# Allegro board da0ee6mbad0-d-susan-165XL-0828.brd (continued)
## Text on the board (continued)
User.45: C1 | C2 | R197 | R199 | C3 | T1 | R6 | R4 | TP1 | R12 | R11 | R10 | R13 | C4 | C5 | C6 | TP2 | R18 | R26 | R27 | R28 | R29 | R30 | R31 | R32 | C20 | C22 | C34 | C39 | C40 | R40 | C46 | C49 | C51 | C52 | C53 | C54 | C56 | C57 | C58 | C60 | C62 | C67 | R56 | R60 | C70 | R62 | R63 | R64 | R65 | R66 | R67 | R68 | C72 | C73 | C74 | R75 | C78 | C79 | D3 | R90 | R91 | C80 | R93 | C81 | R94 | T3 | R99 | R101 | R103 | C87 | PR63 | PR65 | PR64 | R106 | TP60 | TP59 | TP61 | R109 | C92 | R114 | TP5 | PC5 | TP8 | TP7 | PC4 | PC9 | C96 | PR6 | PR7 | PC12 | PC14 | PC15 | PC17 | PC18 | PC20 | PC21 | PC22 | PC19 | PC23 | PR18 | TP11 | TP12 | R121 | R122 | R123 | R124 | R125 | R126 | R127 | R128 | R134 | R135 | R136 | R137 | R138 | R139 | R140 | R141 | PR152 | PR153 | R149 | R150 | C102 | R151 | R148 | PC27 | R161 | C111 | C112 | C113 | R166 | R167 | C375 | TP14 | PC30 | TP18 | TP20 | TP23 | TP30 | C122 | C121 | TP28 | TP26 | TP24 | C345 | R382 | C340 | C343 | C341 | C344 | C342 | PR39 | R400 | C369 | R191 | R186 | R185 | C362 | C361 | R190 | C371 | TP40 | TP34 | TP37 | TP41 | TP36 | TP31 | TP35 | TP39 | TP33 | C366 | C365 | TP32 | C370 | R390 | TP38 | R189 | R188 | PR43 | R207 | R9 | C137 | C140 | R208 | C139 | C138 | C142 | C149 | C148 | C150 | L5 | C147 | R220 | R221 | R218 | C145 | C146 | C141 | C143 | C144 | C152 | C161 | C162 | R224 | R223 | C153 | C154 | C155 | C159 | PR47 | PR49 | C172 | C173 | C174 | R243 | R244 | R245 | R246 | C170 | C171 | C175 | C176 | C177 | C178 | C179 | R247 | R248 | R249 | R250 | R258 | R259 | R260 | C184 | C185 | C186 | R262 | R263 | C188 | C204 | L6 | TP43 | C211 | C214 | C215 | TP44 | C225 | C241 | C239 | C240 | C242 | C243 | C247 | C246 | C244 | C245 | C226 | C221 | C254 | TP46 | TP54 | TP55 | TP45 | TP50 | TP49 | C255 | C256 | C257 | TP47 | TP53 | TP48 | C258 | TP52 | C260 | TP51 | C261 | C262 | C263 | C265 | C267 | C269 | C271 | C272 | C273 | TP56 | C275 | C274 | TP57 | PC44 | C276 | R312 | R313 | R314 | C282 | C283 | C284 | C285 | C286 | C287 | C288 | C292 | R317 | R318 | R321 | R322 | R325 | R328 | PC47 | PR74 | PR75 | PR76 | PR81 | PC74 | R329 | PR88 | PR86 | PC73 | PR87 | PC81 | PR91 | R331 | PR115 | PR55 | PR108 | PC104 | PR109 | PR110 | PR111 | PR112 | PC119 | PC120 | PC123 | PC124 | PC125 | PC128 | PC132 | PR123 | PR124 | PR125 | PR126 | PR127 | PR128 | PC134 | PR136 | PR133 | PR134 | PC133 | PR140 | PR141 | PR139 | PC135 | PR142 | C310 | C314 | R364 | C322 | C321 | C318 | C324 | R378 | C332 | C337 | L16 | C349 | TP62 | TP63 | R384 | C355 | C364 | C363 | C368 | L29 | C374 | L30 | C373 | C358 | 4 | 3 | 6 | TP27 | TP29 | U28 | PD4 | PR143 | PL21 | PL22 | C356 | R3 | R196 | C200 | R14 | C196 | R15 | C7 | C8 | C9 | C10 | C11 | C12 | C13 | C14 | C15 | C16 | R19 | R20 | R21 | R22 | R23 | R24 | C17 | C18 | R286 | C19 | R285 | T2 | R33 | C23 | C24 | C25 | C26 | C21 | C27 | C28 | C30 | C29 | C31 | C32 | C33 | R664 | C35 | C41 | C37 | C38 | C36 | R36 | C43 | C45 | R38 | C44 | R39 | C48 | R41 | C47 | R44 | R45 | C50 | C55 | R46 | R48 | R49 | C59 | R50 | C61 | R52 | C65 | C64 | C66 | R54 | C68 | R55 | R58 | R57 | R61 | R69 | R72 | R73 | R74 | R79 | R80 | R83 | R84 | C77 | R86 | R88 | R89 | R92 | R95 | R96 | R337 | C377 | R97 | C83 | R98 | C378 | C84 | R100 | C85 | R102 | C437 | C86 | R104 | C447 | C452 | C88 | R410 | R105 | C89 | C458 | R107 | C90 | R108 | C91 | C466 | R110 | C93 | C756 | R111 | T4 | R112 | T5 | TP4 | C94 | PC3 | TP6 | D4 | C95 | PR114 | PC8 | PC7 | PR107 | R115 | PC10 | PC11 | PR54 | PC13 | C97 | PC16 | R116 | R117 | R118 | R119 | R120 | PC24 | PC25 | PC26 | PR19 | C98 | C99 | R129 | R130 | R133 | R142 | R143 | PR147 | R144 | PR146 | TP13 | R145 | PR145 | PC137 | C100 | R146 | C101 | R147 | C107 | R154 | C103 | R152 | C104 | C105 | R153 | R156 | C106 | L1 | R155 | R159 | R160 | D7 | C108 | R157 | D8 | R162 | C109 | C114 | C376 | R168 | L2 | R169 | R404 | R170 | T6 | C115 | R407 | R171 | C116 | R406 | PR23 | PR24 | C117 | T7 | PR27 | C118 | PC28 | PC29 | T8 | C119 | C120 | TP15 | TP16 | PC31 | TP17 | R175 | PC32 | T9 | R177 | TP19 | PC33 | PR30 | R178 | PC34 | TP21 | PR32 | TP22 | PR34 | TP25 | PR36 | PR35 | PC35 | C125 | R181 | R182 | T10 | R183 | R184 | T11 | T12 | T13 | C126 | C127 | C128 | T14 | T15 | PR38 | PC40 | PC37 | PR41 | PC38 | PR42 | C134 | C133 | PD1 | R193 | R192 | PC36 | PC39 | C129 | C130 | C132 | C367 | C131 | C135 | C136 | R195 | R209 | R205 | T16 | R210 | R211 | R217 | PC41 | T17 | R225 | R219 | TP42 | R206 | R214 | R215 | R216 | C151 | PR44 | C82 | R213 | PR45 | PC43 | R227 | T18 | R222 | C160 | R229 | PC42 | R235 | R236 | C163 | C164 | R231 | R232 | R233 | R234 | C165 | C167 | C166 | R237 | C168 | R238 | R239 | R240 | R241 | C169 | R242 | R251 | C180 | C181 | C182 | C183 | R252 | R253 | R254 | R255 | R256 | R257 | R264 | R265 | R266 | C187 | C189 | C190 | R261 | C192 | C193 | C194 | C191 | C195 | R267 | R268 | C198 | C197 | C199 | R269 | R270 | C201 | C202 | C203 | R271 | R272 | R273 | C205 | R274 | R276 | C206 | C207 | R277 | R278 | C209 | L7 | R279 | C210 | R280 | C212 | C213 | R281 | R282 | C216 | R283 | R284 | C217 | C218 | C219 | L8 | C220 | C222 | C223 | C224 | C228 | C227 | C230 | C229 | L9 | C231 | C232 | C236 | C237 | C235 | C234 | C238 | C248 | C249 | C251 | C250 | C252 | C253 | R289 | C259 | R290 | R291 | R293 | R296 | PR50 | R297 | PR51 | R298 | C266 | PR52 | C268 | R302 | R303 | C270 | R306 | R305 | R307 | R402 | PR53 | R308 | C277 | C278 | C279 | C280 | C281 | C289 | TP58 | C290 | R316 | C291 | R326 | R323 | R324 | C293 | C294 | PR57 | PC45 | C295 | PC46 | C296 | PC48 | PR61 | PC53 | PC71 | PR83 | PR84 | C297 | PR94 | PC80 | PR96 | PR99 | R330 | PC86 | R332 | R333 | PC93 | R334 | R336 | R335 | R338 | C298 | C299 | R340 | R341 | R342 | R343 | C301 | C302 | R345 | C303 | PC121 | R348 | R349 | R350 | PR116 | PC126 | PC131 | PR132 | PR129 | SS1 | SS2 | PR135 | C307 | PR144 | C306 | C305 | C313 | C311 | C304 | C312 | C315 | C316 | C317 | C320 | R359 | C323 | R362 | C325 | C319 | R369 | C328 | R366 | C327 | C326 | C331 | C329 | R370 | C334 | R379 | C336 | C330 | C339 | R380 | C335 | C338 | C346 | L21 | C350 | L22 | C351 | C352 | L23 | C353 | L24 | C354 | R385 | C372 | L31 | L28 | C357 | C359 | SS3 | HOLE1 | HOLE3 | HOLE2 | 2 | Q1 | Q22 | Q3 | Q2 | HOLE4 | Q4 | Q5 | Q18 | PC1 | PC2 | Q6 | PQ1 | Q8 | F1 | Q9 | Q7 | 5 | PQ13 | PQ12 | 8 | HOLE5 | Y1 | Q10 | HOLE6 | PQ2 | PQ3 | PQ4 | L4 | HOLE13 | Q13 | Q14 | Q15 | Q16 | C156 | C157 | PQ5 | HOLE9 | HOLE7 | U30 | Y4 | PU3 | PC51 | PC52 | PC49 | PC50 | PL1 | PL2 | PC54 | PC55 | PL5 | PC56 | PL3 | PL4 | PC68 | PC70 | PC69 | PC76 | PC75 | PC77 | PC85 | PC89 | PC90 | PC91 | PL15 | Q17 | PL16 | PC97 | PC98 | PC110 | PC105 | PC106 | PC107 | PC108 | PC109 | PC118 | PU8 | 10 | D9 | HOLE10 | LED3 | U1 | U2 | HOLE12 | 74 | SW2 | 20 | U3 | SW3 | C42 | 60 | C69 | C71 | CN1 | C75 | U4 | R85 | 31 | 30 | U5 | SW4 | E | C | A | D | B | U7 | U8 | CN3 | 1 | 19 | HOLE11 | 25 | 36 | D6 | D5 | 24 | 37 | U10 | U11 | 7 | 13 | 48 | HE1 | C110 | H | F | U37 | J | G | 9 | J1 | U12 | PU1 | C123 | C124 | L3 | C347 | C348 | 11 | CN4 | 12 | U14 | 21 | CN5 | U15 | PAD1 | U16 | U17 | U20 | U18 | U19 | U21 | CN6 | PU2 | 75 | CN7 | P | K | M | T | U | R | N | L | AH | AG | AF | AE | AD | AC | U22 | AB | AA | U23 | U24 | U25 | Y2 | U26 | 15 | U27 | 17 | 16 | 14 | 59 | 58 | 57 | 56 | CN8 | 55 | 54 | 53 | 52 | 51 | 50 | 49 | 47 | 46 | 44 | 45 | 43 | 40 | 41 | 39 | 33 | C264 | 29 | U29 | CN9 | Y3 | AL | AP | BM | AY | BC | BF | BJ | W | AU | BR | BV | PQ7 | PQ8 | PR666 | PQ9 | PD2 | 18 | PL6 | PU5 | PC79 | PU6 | PC82 | PC83 | PC84 | PC87 | PC88 | PC99 | PC100 | PC101 | PC102 | PC103 | U31 | PC111 | PC112 | PC113 | PC114 | PC115 | PC116 | PC117 | U32 | PC122 | PL19 | PL20 | PU7 | PR119 | PC129 | PC130 | PC127 | PR130 | C308 | C309 | R355 | U33 | U34 | C333 | CN12 | CN13 | L27 | CN15 | U36 | CT1 | CN14 | U35 | CT2 | Q12 | Q11 | U13 | SW1 | LED1 | R663 | D1 | C76 | D2 | PC6 | PR12 | RP1 | PR151 | R164 | PR1 | PR120 | Q23 | PQ6 | HOLE8 | C158 | PC57 | PC58 | PC59 | PC60 | PC61 | PC62 | PC63 | PC64 | PC65 | PC66 | PL7 | PQ10 | PL8 | PL9 | PC72 | PC78 | PL10 | PL11 | PL12 | PL13 | PL14 | PC94 | PC95 | PL17 | PL18 | PQ11 | PC136 | LED2 | PAD2 | CN2 | Y | V | L10 | L11 | L12 | L13 | R667 | L14 | PD3 | PR79 | PC67 | PU4 | PC92 | PC96 | C300 | CN10 | CN11 | C360 | R7 | C758 | C757 | R87 | PR149 | PR150 | PR20 | R668 | R408 | R397 | R394 | R393 | R392 | R391 | R200 | R275 | R299 | R300 | R309 | R310 | R304 | R319 | PR67 | PR68 | PR80 | PR100 | R356 | R357 | R358 | R367 | L15 | R398 | R399 | R17 | R34 | R35 | R37 | R42 | R70 | R81 | R113 | PR3 | PR4 | PR8 | PR16 | PR148 | PR29 | PR31 | PR33 | R204 | R212 | R311 | R228 | R292 | R294 | R295 | R315 | PR58 | PR60 | PR85 | PR89 | PR93 | R339 | R346 | R347 | R361 | R372 | R376 | R381 | L18 | L20 | R388 | R1 | R198 | R669 | R43 | R47 | R59 | R77 | R78 | PR2 | PR14 | PR17 | R131 | R132 | R670 | PR22 | R411 | PR25 | R179 | R180 | R187 | R8 | R201 | R202 | R230 | R301 | R320 | PR66 | PR71 | PR69 | PR70 | PR77 | PR137 | PR138 | R352 | R353 | R354 | L25 | L26 | R396 | R395 | R401 | R2 | R16 | R25 | R53 | R71 | R76 | R82 | R158 | R163 | R172 | PR26 | R173 | PR28 | R174 | R176 | PR37 | R383 | R194 | R203 | R226 | R327 | PR59 | PR92 | PR95 | R344 | PR117 | PR118 | PR122 | R351 | R360 | R363 | R365 | R368 | R371 | R374 | R377 | R375 | R373 | L17 | L19 | R387 | R389 | R386 | XY-Check acute:Aug 28 11:05:46 2013 | XY-Check cline width:Aug 28 11:13:00 2013 | XY-Check rotation:Aug 28 11:42:44 2013 | XY-Check txt overlap:Aug 28 11:42:36 2013 | XY-Check txt:Aug 28 11:43:04 2013 | XY-Cross plane-IN2-SVCC2:Aug 28 11:08:34 2013 | XY-Cross plane-IN3-SGND2:Aug 28 11:08:40 2013 | XY-Dxf to pin check:Aug 28 10:59:41 2013 | XY-Etch cross-GND1-IN2:Aug 28 11:08:34 2013 | XY-Etch cross-IN3-GND3:Aug 28 11:08:37 2013 | XY-Etch cross-IN4-BOTTOM:Aug 28 11:08:42 2013 | XY-Etch cross-TOP-IN1:Aug 28 11:08:33 2013 | XY-Etch ref-IN2-SVCC2:Aug 28 11:08:37 2013 | XY-Etch ref-IN3-SGND2:Aug 28 11:08:42 2013 | XY-Mask check:Aug 28 11:15:02 2013 | XY-NO Route Under Component:Aug 28 11:14:01 2013 | XY-Norefdes:Aug 28 11:41:04 2013 | XY-Outline check:Aug 28 11:14:09 2013 | XY-Plane net check:Aug 28 11:00:45 2013 | XY-Prop check:Aug 28 11:08:28 2013 | XY-Symbol cross:Aug 28 11:04:05 2013 | XY-Via check:Aug 28 11:13:13 2013 | check acute:Aug 21 18:01:22 2013 | create nettxt:Aug 24 16:29:16 2013 | create plane:Aug 28 10:41:35 2013 | cross plane-IN2-SVCC2:Aug 26 08:58:37 2013 | cross plane-IN3-SGND2:Aug 26 08:58:39 2013 | etch cross-GND1-IN2:Aug 26 08:58:36 2013 | etch cross-IN3-GND3:Aug 26 08:58:37 2013 | etch cross-IN4-BOTTOM:Aug 26 08:58:40 2013 | etch cross-TOP-IN1:Aug 26 08:58:36 2013 | etch ref-IN2-SVCC2:Aug 26 08:58:37 2013 | etch ref-IN3-SGND2:Aug 26 08:58:40 2013 | prop check:Aug 26 08:58:34 2013 | via check:Aug 26 08:58:52 2013 | DA0EE6MBAB0 | REV:B | GND | X | MODEL:EE6 | FIGURE | TYPE | Circle | SIZE | 4.0 | 8.0 | DRILL CHART: IN1 to GND1 | ALL UNITS ARE IN MILS | DRILL CHART: GND1 to IN2 | DRILL CHART: TOP to IN1 | DRILL CHART: GND1 to GND3 | PLATED | ROTATION | - | QTY | 2036 | 831 | 2062 | 803 | Oblong | 10.0 | 12.0 | 14.0 | 71.0 | 79.0 | 35.0 | 43.0 | 63.0 | 100.0 | DRILL CHART: TOP to BOTTOM | DRILL CHART: IN4 to BOTTOM | DRILL CHART: GND3 to IN4 | DRILL CHART: IN3 to GND3 | NON-PLATED | 90.000 | 419 | 110 | 558 | 4559 | 4036 | 1334 | TOTAL HOLES:
